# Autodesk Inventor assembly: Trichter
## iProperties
Created: 2010-10
Part Number: Trichter
Document SubType Name: Assembly
Designer: M.Grouls
Mass: 4.27567e+06 g
Surface Area: 101252 cm^2
Volume: 545334 cm^3
Density: 7.84047 g/cm^3
Author: M.Grouls
